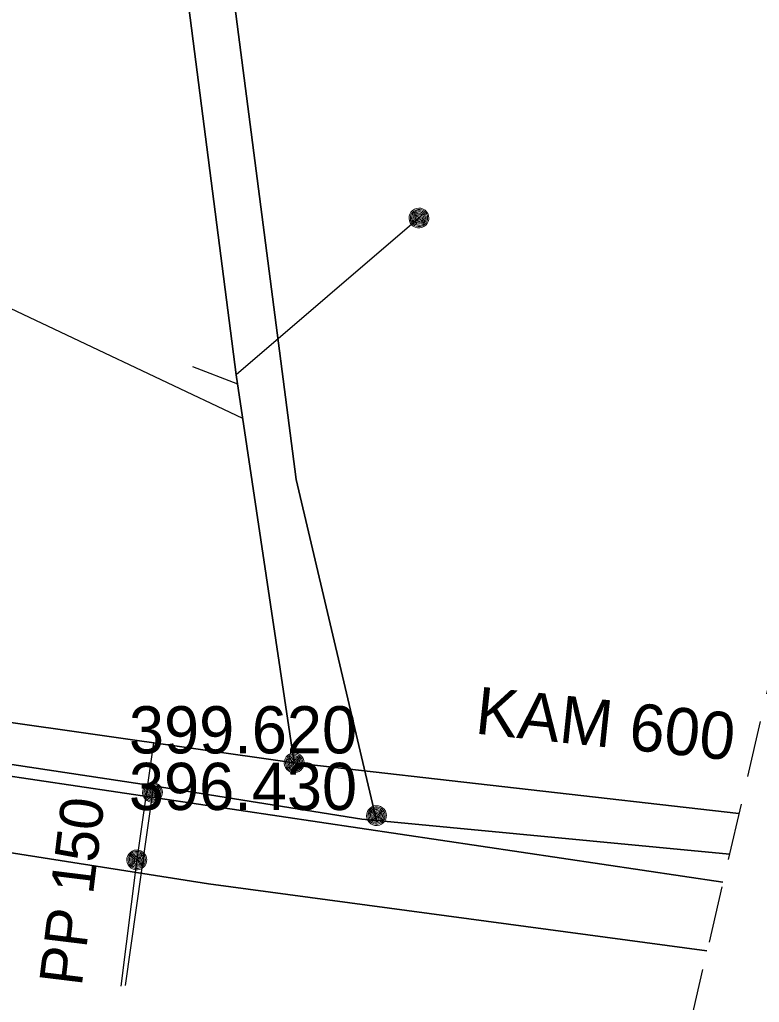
# Model space of a CAD drawing. Extents: x -866761 to -866592, y -1013996 to -1013877.
# Drawn here: x -866629.36 to -866612.12, y -1013980.56 to -1013957.66 of the extents above; entities that cross this region are included whole.
import ezdxf

# ---------------------------------------------------------------- set-up
doc = ezdxf.new("R2010")
doc.units = 0
doc.header["$LTSCALE"] = 0.44
doc.linetypes.add('MEDIUM_DASHED', pattern=[4.5, 3, -1.5])
for name, color, linetype, lineweight in [('1', 7, 'Continuous', 35), ('12', 7, 'Continuous', 13), ('21', 7, 'Continuous', 35), ('23', 7, 'Continuous', 25), ('25', 7, 'Continuous', 13), ('3', 7, 'Continuous', 25), ('32', 7, 'Continuous', 13), ('62', 7, 'MEDIUM_DASHED', 25)]:
    doc.layers.add(name, color=color, linetype=linetype, lineweight=lineweight)

msp = doc.modelspace()

# ---------------------------------------------------------------- linework, layer by layer
at = {"layer": '1'}
msp.add_line((-866612.967, -1013977.763), (-866734.931, -1013959.586), dxfattribs=at)
for points in [[(-866621.036, -1013976.325), (-866622.91, -1013968.373), (-866626.376, -1013941.619), (-866627.386, -1013933.289), (-866629.697, -1013910.45), (-866632.18, -1013888.99), (-866632.46, -1013887.48), (-866632.668, -1013884.429)], [(-866612.815, -1013977.108), (-866621.035, -1013976.325), (-866621.378, -1013976.297), (-866626.243, -1013975.519), (-866632.94, -1013974.51), (-866645.03, -1013972.86), (-866647.305, -1013972.501), (-866654.48, -1013971.31), (-866668.882, -1013969.171), (-866678.229, -1013967.78), (-866685.446, -1013966.718), (-866689.8, -1013966.06), (-866697.865, -1013964.927), (-866723.097, -1013961.352), (-866726.923, -1013960.77), (-866727.214, -1013960.734), (-866737.38, -1013959.64), (-866746.09, -1013958.48), (-866747.84, -1013958.25), (-866748.13, -1013958.99), (-866750.15, -1013958.69)], [(-866613.338, -1013979.363), (-866624.951, -1013977.802), (-866715.256, -1013963.593), (-866735.102, -1013960.577)]]:
    msp.add_lwpolyline(points, dxfattribs=at)
at = {"layer": '12'}
for points in [[(-866626.029, -1013975.67), (-866626.035, -1013975.618), (-866626.052, -1013975.568), (-866626.081, -1013975.524), (-866626.118, -1013975.487), (-866626.163, -1013975.46), (-866626.213, -1013975.443), (-866626.266, -1013975.439), (-866626.318, -1013975.446), (-866626.367, -1013975.465), (-866626.41, -1013975.494), (-866626.446, -1013975.533), (-866626.472, -1013975.578), (-866626.488, -1013975.629), (-866626.491, -1013975.681), (-866626.483, -1013975.733), (-866626.463, -1013975.782), (-866626.432, -1013975.825), (-866626.393, -1013975.859), (-866626.347, -1013975.885), (-866626.296, -1013975.899), (-866626.243, -1013975.901), (-866626.192, -1013975.891), (-866626.144, -1013975.87), (-866626.101, -1013975.839), (-866626.067, -1013975.798), (-866626.043, -1013975.752), (-866626.031, -1013975.701)], [(-866626.059, -1013975.67), (-866626.065, -1013975.621), (-866626.082, -1013975.575), (-866626.11, -1013975.535), (-866626.147, -1013975.503), (-866626.191, -1013975.481), (-866626.239, -1013975.47), (-866626.288, -1013975.47), (-866626.335, -1013975.483), (-866626.378, -1013975.507), (-866626.414, -1013975.54), (-866626.441, -1013975.581), (-866626.457, -1013975.628), (-866626.461, -1013975.677), (-866626.454, -1013975.725), (-866626.435, -1013975.77), (-866626.405, -1013975.81), (-866626.367, -1013975.841), (-866626.323, -1013975.861), (-866626.275, -1013975.871), (-866626.226, -1013975.869), (-866626.179, -1013975.854), (-866626.136, -1013975.829), (-866626.102, -1013975.795), (-866626.076, -1013975.753), (-866626.062, -1013975.706)], [(-866626.089, -1013975.67), (-866626.095, -1013975.625), (-866626.112, -1013975.583), (-866626.14, -1013975.548), (-866626.176, -1013975.521), (-866626.218, -1013975.504), (-866626.263, -1013975.499), (-866626.308, -1013975.505), (-866626.349, -1013975.524), (-866626.384, -1013975.552), (-866626.411, -1013975.589), (-866626.427, -1013975.631), (-866626.431, -1013975.676), (-866626.424, -1013975.721), (-866626.405, -1013975.762), (-866626.376, -1013975.796), (-866626.339, -1013975.822), (-866626.296, -1013975.838), (-866626.251, -1013975.841), (-866626.206, -1013975.833), (-866626.166, -1013975.813), (-866626.132, -1013975.784), (-866626.106, -1013975.746), (-866626.092, -1013975.703)], [(-866626.119, -1013975.67), (-866626.124, -1013975.629), (-866626.142, -1013975.592), (-866626.169, -1013975.561), (-866626.204, -1013975.54), (-866626.244, -1013975.529), (-866626.285, -1013975.531), (-866626.324, -1013975.544), (-866626.358, -1013975.568), (-866626.383, -1013975.6), (-866626.398, -1013975.638), (-866626.401, -1013975.679), (-866626.393, -1013975.719), (-866626.373, -1013975.755), (-866626.344, -1013975.784), (-866626.307, -1013975.803), (-866626.267, -1013975.811), (-866626.226, -1013975.807), (-866626.188, -1013975.792), (-866626.156, -1013975.766), (-866626.133, -1013975.732), (-866626.12, -1013975.693)], [(-866626.149, -1013975.67), (-866626.154, -1013975.634), (-866626.172, -1013975.602), (-866626.198, -1013975.577), (-866626.232, -1013975.562), (-866626.268, -1013975.559), (-866626.303, -1013975.567), (-866626.334, -1013975.587), (-866626.357, -1013975.615), (-866626.37, -1013975.649), (-866626.37, -1013975.686), (-866626.359, -1013975.721), (-866626.338, -1013975.75), (-866626.308, -1013975.771), (-866626.273, -1013975.781), (-866626.236, -1013975.779), (-866626.202, -1013975.765), (-866626.175, -1013975.742), (-866626.156, -1013975.71), (-866626.149, -1013975.675)], [(-866626.179, -1013975.67), (-866626.184, -1013975.639), (-866626.201, -1013975.613), (-866626.227, -1013975.596), (-866626.257, -1013975.589), (-866626.288, -1013975.593), (-866626.315, -1013975.61), (-866626.333, -1013975.634), (-866626.341, -1013975.665), (-866626.337, -1013975.695), (-866626.322, -1013975.723), (-866626.298, -1013975.742), (-866626.268, -1013975.751), (-866626.237, -1013975.748), (-866626.209, -1013975.734), (-866626.189, -1013975.71), (-866626.179, -1013975.681)], [(-866626.209, -1013975.67), (-866626.214, -1013975.646), (-866626.231, -1013975.628), (-866626.254, -1013975.619), (-866626.278, -1013975.622), (-866626.299, -1013975.636), (-866626.31, -1013975.658), (-866626.31, -1013975.683), (-866626.298, -1013975.704), (-866626.278, -1013975.718), (-866626.253, -1013975.721), (-866626.23, -1013975.712), (-866626.214, -1013975.694)], [(-866626.239, -1013975.67), (-866626.244, -1013975.655), (-866626.259, -1013975.649), (-866626.274, -1013975.653), (-866626.281, -1013975.667), (-866626.277, -1013975.682), (-866626.264, -1013975.691), (-866626.249, -1013975.688), (-866626.239, -1013975.676)], [(-866620.809, -1013976.21), (-866620.815, -1013976.158), (-866620.832, -1013976.108), (-866620.861, -1013976.064), (-866620.898, -1013976.027), (-866620.943, -1013976), (-866620.993, -1013975.983), (-866621.046, -1013975.979), (-866621.098, -1013975.986), (-866621.147, -1013976.005), (-866621.19, -1013976.034), (-866621.226, -1013976.073), (-866621.252, -1013976.118), (-866621.268, -1013976.169), (-866621.271, -1013976.221), (-866621.263, -1013976.273), (-866621.243, -1013976.322), (-866621.212, -1013976.365), (-866621.173, -1013976.399), (-866621.127, -1013976.425), (-866621.076, -1013976.439), (-866621.023, -1013976.441), (-866620.972, -1013976.431), (-866620.924, -1013976.41), (-866620.881, -1013976.379), (-866620.847, -1013976.338), (-866620.823, -1013976.292), (-866620.811, -1013976.241)], [(-866620.839, -1013976.21), (-866620.845, -1013976.161), (-866620.862, -1013976.115), (-866620.89, -1013976.075), (-866620.927, -1013976.043), (-866620.971, -1013976.021), (-866621.019, -1013976.01), (-866621.068, -1013976.01), (-866621.115, -1013976.023), (-866621.158, -1013976.047), (-866621.194, -1013976.08), (-866621.221, -1013976.121), (-866621.237, -1013976.168), (-866621.241, -1013976.217), (-866621.234, -1013976.265), (-866621.215, -1013976.31), (-866621.185, -1013976.35), (-866621.147, -1013976.381), (-866621.103, -1013976.401), (-866621.055, -1013976.411), (-866621.006, -1013976.409), (-866620.959, -1013976.394), (-866620.916, -1013976.369), (-866620.882, -1013976.335), (-866620.856, -1013976.293), (-866620.842, -1013976.246)], [(-866620.869, -1013976.21), (-866620.875, -1013976.165), (-866620.892, -1013976.123), (-866620.92, -1013976.088), (-866620.956, -1013976.061), (-866620.998, -1013976.044), (-866621.043, -1013976.039), (-866621.088, -1013976.045), (-866621.129, -1013976.064), (-866621.164, -1013976.092), (-866621.191, -1013976.129), (-866621.207, -1013976.171), (-866621.211, -1013976.216), (-866621.204, -1013976.261), (-866621.185, -1013976.302), (-866621.156, -1013976.336), (-866621.119, -1013976.362), (-866621.076, -1013976.378), (-866621.031, -1013976.381), (-866620.986, -1013976.373), (-866620.946, -1013976.353), (-866620.912, -1013976.324), (-866620.886, -1013976.286), (-866620.872, -1013976.243)], [(-866620.899, -1013976.21), (-866620.904, -1013976.169), (-866620.922, -1013976.132), (-866620.949, -1013976.101), (-866620.984, -1013976.08), (-866621.024, -1013976.069), (-866621.065, -1013976.071), (-866621.104, -1013976.084), (-866621.138, -1013976.108), (-866621.163, -1013976.14), (-866621.178, -1013976.178), (-866621.181, -1013976.219), (-866621.173, -1013976.259), (-866621.153, -1013976.295), (-866621.124, -1013976.324), (-866621.087, -1013976.343), (-866621.047, -1013976.351), (-866621.006, -1013976.347), (-866620.968, -1013976.332), (-866620.936, -1013976.306), (-866620.913, -1013976.272), (-866620.9, -1013976.233)], [(-866620.929, -1013976.21), (-866620.934, -1013976.174), (-866620.952, -1013976.142), (-866620.978, -1013976.117), (-866621.012, -1013976.102), (-866621.048, -1013976.099), (-866621.083, -1013976.107), (-866621.114, -1013976.127), (-866621.137, -1013976.155), (-866621.15, -1013976.189), (-866621.15, -1013976.226), (-866621.139, -1013976.261), (-866621.118, -1013976.29), (-866621.088, -1013976.311), (-866621.053, -1013976.321), (-866621.016, -1013976.319), (-866620.982, -1013976.305), (-866620.955, -1013976.282), (-866620.936, -1013976.25), (-866620.929, -1013976.215)], [(-866620.959, -1013976.21), (-866620.964, -1013976.179), (-866620.981, -1013976.153), (-866621.007, -1013976.136), (-866621.037, -1013976.129), (-866621.068, -1013976.133), (-866621.095, -1013976.15), (-866621.113, -1013976.174), (-866621.121, -1013976.205), (-866621.117, -1013976.235), (-866621.102, -1013976.263), (-866621.078, -1013976.282), (-866621.048, -1013976.291), (-866621.017, -1013976.288), (-866620.989, -1013976.274), (-866620.969, -1013976.25), (-866620.959, -1013976.221)], [(-866620.989, -1013976.21), (-866620.994, -1013976.186), (-866621.011, -1013976.168), (-866621.034, -1013976.159), (-866621.058, -1013976.162), (-866621.079, -1013976.176), (-866621.09, -1013976.198), (-866621.09, -1013976.223), (-866621.078, -1013976.244), (-866621.058, -1013976.258), (-866621.033, -1013976.261), (-866621.01, -1013976.252), (-866620.994, -1013976.234)], [(-866621.019, -1013976.21), (-866621.024, -1013976.195), (-866621.039, -1013976.189), (-866621.054, -1013976.193), (-866621.061, -1013976.207), (-866621.057, -1013976.222), (-866621.044, -1013976.231), (-866621.029, -1013976.228), (-866621.019, -1013976.216)]]:
    msp.add_lwpolyline(points, close=True, dxfattribs=at)
at = {"layer": '21'}
for p, q in [((-866647.459, -1013971.5), (-866622.959, -1013974.98)), ((-866622.959, -1013974.98), (-866612.595, -1013976.159))]:
    msp.add_line(p, q, dxfattribs=at)
msp.add_lwpolyline([(-866627.91, -1013938.45), (-866629.08, -1013928.9), (-866624.31, -1013965.933), (-866624.165, -1013966.919), (-866622.957, -1013974.98)], dxfattribs=at)
at = {"layer": '23'}
for p, q in [((-866636.279, -1013961.21), (-866624.162, -1013966.944)), ((-866620.05, -1013962.28), (-866624.31, -1013965.933)), ((-866625.33, -1013965.74), (-866624.279, -1013966.143))]:
    msp.add_line(p, q, dxfattribs=at)
msp.add_lwpolyline([(-866626.236, -1013974.515), (-866626.63, -1013977.29), (-866627, -1013980.185)], dxfattribs=at)
at = {"layer": '25'}
for points in [[(-866619.819, -1013962.28), (-866619.825, -1013962.228), (-866619.842, -1013962.178), (-866619.871, -1013962.134), (-866619.908, -1013962.097), (-866619.953, -1013962.07), (-866620.003, -1013962.053), (-866620.056, -1013962.049), (-866620.108, -1013962.056), (-866620.157, -1013962.075), (-866620.2, -1013962.104), (-866620.236, -1013962.143), (-866620.262, -1013962.188), (-866620.278, -1013962.239), (-866620.281, -1013962.291), (-866620.273, -1013962.343), (-866620.253, -1013962.392), (-866620.222, -1013962.435), (-866620.183, -1013962.469), (-866620.137, -1013962.495), (-866620.086, -1013962.509), (-866620.033, -1013962.511), (-866619.982, -1013962.501), (-866619.934, -1013962.48), (-866619.891, -1013962.449), (-866619.857, -1013962.408), (-866619.833, -1013962.362), (-866619.821, -1013962.311)], [(-866619.849, -1013962.28), (-866619.855, -1013962.231), (-866619.872, -1013962.185), (-866619.9, -1013962.145), (-866619.937, -1013962.113), (-866619.981, -1013962.091), (-866620.029, -1013962.08), (-866620.078, -1013962.08), (-866620.125, -1013962.093), (-866620.168, -1013962.117), (-866620.204, -1013962.15), (-866620.231, -1013962.191), (-866620.247, -1013962.238), (-866620.251, -1013962.287), (-866620.244, -1013962.335), (-866620.225, -1013962.38), (-866620.195, -1013962.42), (-866620.157, -1013962.451), (-866620.113, -1013962.471), (-866620.065, -1013962.481), (-866620.016, -1013962.479), (-866619.969, -1013962.464), (-866619.926, -1013962.439), (-866619.892, -1013962.405), (-866619.866, -1013962.363), (-866619.852, -1013962.316)], [(-866619.879, -1013962.28), (-866619.885, -1013962.235), (-866619.902, -1013962.193), (-866619.93, -1013962.158), (-866619.966, -1013962.131), (-866620.008, -1013962.114), (-866620.053, -1013962.109), (-866620.098, -1013962.115), (-866620.139, -1013962.134), (-866620.174, -1013962.162), (-866620.201, -1013962.199), (-866620.217, -1013962.241), (-866620.221, -1013962.286), (-866620.214, -1013962.331), (-866620.195, -1013962.372), (-866620.166, -1013962.406), (-866620.129, -1013962.432), (-866620.086, -1013962.448), (-866620.041, -1013962.451), (-866619.996, -1013962.443), (-866619.956, -1013962.423), (-866619.922, -1013962.394), (-866619.896, -1013962.356), (-866619.882, -1013962.313)], [(-866619.909, -1013962.28), (-866619.914, -1013962.239), (-866619.932, -1013962.202), (-866619.959, -1013962.171), (-866619.994, -1013962.15), (-866620.034, -1013962.139), (-866620.075, -1013962.141), (-866620.114, -1013962.154), (-866620.148, -1013962.178), (-866620.173, -1013962.21), (-866620.188, -1013962.248), (-866620.191, -1013962.289), (-866620.183, -1013962.329), (-866620.163, -1013962.365), (-866620.134, -1013962.394), (-866620.097, -1013962.413), (-866620.057, -1013962.421), (-866620.016, -1013962.417), (-866619.978, -1013962.402), (-866619.946, -1013962.376), (-866619.923, -1013962.342), (-866619.91, -1013962.303)], [(-866619.939, -1013962.28), (-866619.944, -1013962.244), (-866619.962, -1013962.212), (-866619.988, -1013962.187), (-866620.022, -1013962.172), (-866620.058, -1013962.169), (-866620.093, -1013962.177), (-866620.124, -1013962.197), (-866620.147, -1013962.225), (-866620.16, -1013962.259), (-866620.16, -1013962.296), (-866620.149, -1013962.331), (-866620.128, -1013962.36), (-866620.098, -1013962.381), (-866620.063, -1013962.391), (-866620.026, -1013962.389), (-866619.992, -1013962.375), (-866619.965, -1013962.352), (-866619.946, -1013962.32), (-866619.939, -1013962.285)], [(-866619.969, -1013962.28), (-866619.974, -1013962.249), (-866619.991, -1013962.223), (-866620.017, -1013962.206), (-866620.047, -1013962.199), (-866620.078, -1013962.203), (-866620.105, -1013962.22), (-866620.123, -1013962.244), (-866620.131, -1013962.275), (-866620.127, -1013962.305), (-866620.112, -1013962.333), (-866620.088, -1013962.352), (-866620.058, -1013962.361), (-866620.027, -1013962.358), (-866619.999, -1013962.344), (-866619.979, -1013962.32), (-866619.969, -1013962.291)], [(-866619.999, -1013962.28), (-866620.004, -1013962.256), (-866620.021, -1013962.238), (-866620.044, -1013962.229), (-866620.068, -1013962.232), (-866620.089, -1013962.246), (-866620.1, -1013962.268), (-866620.1, -1013962.293), (-866620.088, -1013962.314), (-866620.068, -1013962.328), (-866620.043, -1013962.331), (-866620.02, -1013962.322), (-866620.004, -1013962.304)], [(-866620.029, -1013962.28), (-866620.034, -1013962.265), (-866620.049, -1013962.259), (-866620.064, -1013962.263), (-866620.071, -1013962.277), (-866620.067, -1013962.292), (-866620.054, -1013962.301), (-866620.039, -1013962.298), (-866620.029, -1013962.286)]]:
    msp.add_lwpolyline(points, close=True, dxfattribs=at)
at = {"layer": '3'}
msp.add_lwpolyline([(-866626.243, -1013975.519), (-866626.26, -1013975.67), (-866626.9, -1013980.17)], dxfattribs=at)
at = {"layer": '32'}
for points in [[(-866622.728, -1013974.98), (-866622.734, -1013974.928), (-866622.751, -1013974.878), (-866622.78, -1013974.834), (-866622.817, -1013974.797), (-866622.862, -1013974.77), (-866622.912, -1013974.753), (-866622.965, -1013974.749), (-866623.017, -1013974.756), (-866623.066, -1013974.775), (-866623.109, -1013974.804), (-866623.145, -1013974.843), (-866623.171, -1013974.888), (-866623.187, -1013974.939), (-866623.19, -1013974.991), (-866623.182, -1013975.043), (-866623.162, -1013975.092), (-866623.131, -1013975.135), (-866623.092, -1013975.169), (-866623.046, -1013975.195), (-866622.995, -1013975.209), (-866622.942, -1013975.211), (-866622.891, -1013975.201), (-866622.843, -1013975.18), (-866622.8, -1013975.149), (-866622.766, -1013975.108), (-866622.742, -1013975.062), (-866622.73, -1013975.011)], [(-866622.758, -1013974.98), (-866622.764, -1013974.931), (-866622.781, -1013974.885), (-866622.809, -1013974.845), (-866622.846, -1013974.813), (-866622.89, -1013974.791), (-866622.938, -1013974.78), (-866622.987, -1013974.78), (-866623.034, -1013974.793), (-866623.077, -1013974.817), (-866623.113, -1013974.85), (-866623.14, -1013974.891), (-866623.156, -1013974.938), (-866623.16, -1013974.987), (-866623.153, -1013975.035), (-866623.134, -1013975.08), (-866623.104, -1013975.12), (-866623.066, -1013975.151), (-866623.022, -1013975.171), (-866622.974, -1013975.181), (-866622.925, -1013975.179), (-866622.878, -1013975.164), (-866622.835, -1013975.139), (-866622.801, -1013975.105), (-866622.775, -1013975.063), (-866622.761, -1013975.016)], [(-866622.788, -1013974.98), (-866622.794, -1013974.935), (-866622.811, -1013974.893), (-866622.839, -1013974.858), (-866622.875, -1013974.831), (-866622.917, -1013974.814), (-866622.962, -1013974.809), (-866623.007, -1013974.815), (-866623.048, -1013974.834), (-866623.083, -1013974.862), (-866623.11, -1013974.899), (-866623.126, -1013974.941), (-866623.13, -1013974.986), (-866623.123, -1013975.031), (-866623.104, -1013975.072), (-866623.075, -1013975.106), (-866623.038, -1013975.132), (-866622.995, -1013975.148), (-866622.95, -1013975.151), (-866622.905, -1013975.143), (-866622.865, -1013975.123), (-866622.831, -1013975.094), (-866622.805, -1013975.056), (-866622.791, -1013975.013)], [(-866622.818, -1013974.98), (-866622.823, -1013974.939), (-866622.841, -1013974.902), (-866622.868, -1013974.871), (-866622.903, -1013974.85), (-866622.943, -1013974.839), (-866622.984, -1013974.841), (-866623.023, -1013974.854), (-866623.057, -1013974.878), (-866623.082, -1013974.91), (-866623.097, -1013974.948), (-866623.1, -1013974.989), (-866623.092, -1013975.029), (-866623.072, -1013975.065), (-866623.043, -1013975.094), (-866623.006, -1013975.113), (-866622.966, -1013975.121), (-866622.925, -1013975.117), (-866622.887, -1013975.102), (-866622.855, -1013975.076), (-866622.832, -1013975.042), (-866622.819, -1013975.003)], [(-866622.848, -1013974.98), (-866622.853, -1013974.944), (-866622.871, -1013974.912), (-866622.897, -1013974.887), (-866622.931, -1013974.872), (-866622.967, -1013974.869), (-866623.002, -1013974.877), (-866623.033, -1013974.897), (-866623.056, -1013974.925), (-866623.069, -1013974.959), (-866623.069, -1013974.996), (-866623.058, -1013975.031), (-866623.037, -1013975.06), (-866623.007, -1013975.081), (-866622.972, -1013975.091), (-866622.935, -1013975.089), (-866622.901, -1013975.075), (-866622.874, -1013975.052), (-866622.855, -1013975.02), (-866622.848, -1013974.985)], [(-866622.878, -1013974.98), (-866622.883, -1013974.949), (-866622.9, -1013974.923), (-866622.926, -1013974.906), (-866622.956, -1013974.899), (-866622.987, -1013974.903), (-866623.014, -1013974.92), (-866623.032, -1013974.944), (-866623.04, -1013974.975), (-866623.036, -1013975.005), (-866623.021, -1013975.033), (-866622.997, -1013975.052), (-866622.967, -1013975.061), (-866622.936, -1013975.058), (-866622.908, -1013975.044), (-866622.888, -1013975.02), (-866622.878, -1013974.991)], [(-866622.908, -1013974.98), (-866622.913, -1013974.956), (-866622.93, -1013974.938), (-866622.953, -1013974.929), (-866622.977, -1013974.932), (-866622.998, -1013974.946), (-866623.009, -1013974.968), (-866623.009, -1013974.993), (-866622.997, -1013975.014), (-866622.977, -1013975.028), (-866622.952, -1013975.031), (-866622.929, -1013975.022), (-866622.913, -1013975.004)], [(-866622.938, -1013974.98), (-866622.943, -1013974.965), (-866622.958, -1013974.959), (-866622.973, -1013974.963), (-866622.98, -1013974.977), (-866622.976, -1013974.992), (-866622.963, -1013975.001), (-866622.948, -1013974.998), (-866622.938, -1013974.986)], [(-866626.395, -1013977.244), (-866626.401, -1013977.192), (-866626.418, -1013977.142), (-866626.447, -1013977.098), (-866626.484, -1013977.061), (-866626.529, -1013977.034), (-866626.579, -1013977.017), (-866626.632, -1013977.013), (-866626.684, -1013977.02), (-866626.733, -1013977.039), (-866626.776, -1013977.068), (-866626.812, -1013977.107), (-866626.838, -1013977.152), (-866626.854, -1013977.203), (-866626.857, -1013977.255), (-866626.849, -1013977.307), (-866626.829, -1013977.356), (-866626.798, -1013977.399), (-866626.759, -1013977.433), (-866626.713, -1013977.459), (-866626.662, -1013977.473), (-866626.609, -1013977.475), (-866626.558, -1013977.465), (-866626.51, -1013977.444), (-866626.467, -1013977.413), (-866626.433, -1013977.372), (-866626.409, -1013977.326), (-866626.397, -1013977.275)], [(-866626.425, -1013977.244), (-866626.431, -1013977.195), (-866626.448, -1013977.149), (-866626.476, -1013977.109), (-866626.513, -1013977.077), (-866626.557, -1013977.055), (-866626.605, -1013977.044), (-866626.654, -1013977.044), (-866626.701, -1013977.057), (-866626.744, -1013977.081), (-866626.78, -1013977.114), (-866626.807, -1013977.155), (-866626.823, -1013977.202), (-866626.827, -1013977.251), (-866626.82, -1013977.299), (-866626.801, -1013977.344), (-866626.771, -1013977.384), (-866626.733, -1013977.415), (-866626.689, -1013977.435), (-866626.641, -1013977.445), (-866626.592, -1013977.443), (-866626.545, -1013977.428), (-866626.502, -1013977.403), (-866626.468, -1013977.369), (-866626.442, -1013977.327), (-866626.428, -1013977.28)], [(-866626.455, -1013977.244), (-866626.461, -1013977.199), (-866626.478, -1013977.157), (-866626.506, -1013977.122), (-866626.542, -1013977.095), (-866626.584, -1013977.078), (-866626.629, -1013977.073), (-866626.674, -1013977.079), (-866626.715, -1013977.098), (-866626.75, -1013977.126), (-866626.777, -1013977.163), (-866626.793, -1013977.205), (-866626.797, -1013977.25), (-866626.79, -1013977.295), (-866626.771, -1013977.336), (-866626.742, -1013977.37), (-866626.705, -1013977.396), (-866626.662, -1013977.412), (-866626.617, -1013977.415), (-866626.572, -1013977.407), (-866626.532, -1013977.387), (-866626.498, -1013977.358), (-866626.472, -1013977.32), (-866626.458, -1013977.277)], [(-866626.485, -1013977.244), (-866626.49, -1013977.203), (-866626.508, -1013977.166), (-866626.535, -1013977.135), (-866626.57, -1013977.114), (-866626.61, -1013977.103), (-866626.651, -1013977.105), (-866626.69, -1013977.118), (-866626.724, -1013977.142), (-866626.749, -1013977.174), (-866626.764, -1013977.212), (-866626.767, -1013977.253), (-866626.759, -1013977.293), (-866626.739, -1013977.329), (-866626.71, -1013977.358), (-866626.673, -1013977.377), (-866626.633, -1013977.385), (-866626.592, -1013977.381), (-866626.554, -1013977.366), (-866626.522, -1013977.34), (-866626.499, -1013977.306), (-866626.486, -1013977.267)], [(-866626.515, -1013977.244), (-866626.52, -1013977.208), (-866626.538, -1013977.176), (-866626.564, -1013977.151), (-866626.598, -1013977.136), (-866626.634, -1013977.133), (-866626.669, -1013977.141), (-866626.7, -1013977.161), (-866626.723, -1013977.189), (-866626.736, -1013977.223), (-866626.736, -1013977.26), (-866626.725, -1013977.295), (-866626.704, -1013977.324), (-866626.674, -1013977.345), (-866626.639, -1013977.355), (-866626.602, -1013977.353), (-866626.568, -1013977.339), (-866626.541, -1013977.316), (-866626.522, -1013977.284), (-866626.515, -1013977.249)], [(-866626.545, -1013977.244), (-866626.55, -1013977.213), (-866626.567, -1013977.187), (-866626.593, -1013977.17), (-866626.623, -1013977.163), (-866626.654, -1013977.167), (-866626.681, -1013977.184), (-866626.699, -1013977.208), (-866626.707, -1013977.239), (-866626.703, -1013977.269), (-866626.688, -1013977.297), (-866626.664, -1013977.316), (-866626.634, -1013977.325), (-866626.603, -1013977.322), (-866626.575, -1013977.308), (-866626.555, -1013977.284), (-866626.545, -1013977.255)], [(-866626.575, -1013977.244), (-866626.58, -1013977.22), (-866626.597, -1013977.202), (-866626.62, -1013977.193), (-866626.644, -1013977.196), (-866626.665, -1013977.21), (-866626.676, -1013977.232), (-866626.676, -1013977.257), (-866626.664, -1013977.278), (-866626.644, -1013977.292), (-866626.619, -1013977.295), (-866626.596, -1013977.286), (-866626.58, -1013977.268)], [(-866626.605, -1013977.244), (-866626.61, -1013977.229), (-866626.625, -1013977.223), (-866626.64, -1013977.227), (-866626.647, -1013977.241), (-866626.643, -1013977.256), (-866626.63, -1013977.265), (-866626.615, -1013977.262), (-866626.605, -1013977.25)]]:
    msp.add_lwpolyline(points, close=True, dxfattribs=at)
at = {"layer": '62'}
msp.add_lwpolyline([(-866747.317, -1013876.568), (-866591.969, -1013887.219), (-866617.09, -1013995.541), (-866760.581, -1013983.282)], close=True, dxfattribs=at)

# ---------------------------------------------------------------- texts
at = {"layer": '1'}
msp.add_text('KAM 600 ', height=1.1, rotation=354, dxfattribs=at).set_placement((-866618.764, -1013974.295))
at = {"layer": '23'}
msp.add_text('PP 150', height=1, rotation=83, dxfattribs=at).set_placement((-866627.91, -1013980.208))
at = {"layer": '25'}
for s, p in [('399.620 ', (-866626.809, -1013974.76)), ('396.430 ', (-866626.809, -1013976.08))]:
    msp.add_text(s, height=1.1, dxfattribs=at).set_placement(p)

doc.saveas('drawing.dxf')
